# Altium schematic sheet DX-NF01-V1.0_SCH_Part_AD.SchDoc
size A4; SheetNumber: 2; SheetTotal: 2
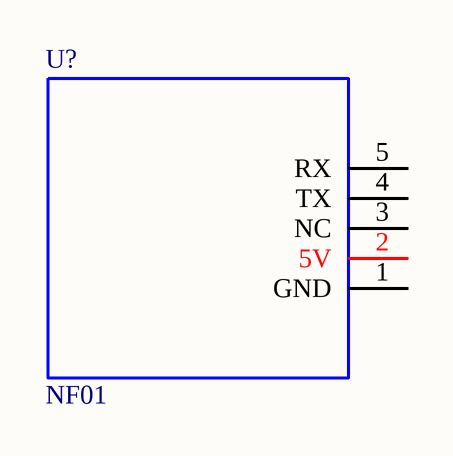
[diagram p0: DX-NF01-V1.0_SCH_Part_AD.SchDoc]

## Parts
U?  NF01

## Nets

Not connected (* = marked no-connect by the designer): U? 1(GND) 2(5V) 3(NC) 4(TX) 5(RX)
